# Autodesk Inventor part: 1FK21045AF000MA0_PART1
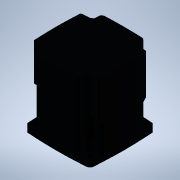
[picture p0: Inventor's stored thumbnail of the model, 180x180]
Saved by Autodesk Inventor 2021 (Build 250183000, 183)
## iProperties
Created: 2025-04
Part Number: 1FK21045AF000MA0_PART1
Material: Generic
Catalog Web Link: www.3dfindit.com
Description: -Servo synchronous motor
Document SubType Name: Modeling
Designer: psAdmin
Mass: 473.602 g
Surface Area: 436.509 cm^2
Volume: 473.602 cm^3
Density: 1 g/cm^3
Appearance: PSOLRGB-176-176-176
Category: PARTsolutions
Title: 1FK21045AF000MA0_PART1
Author: Cadenas PARTsolutions
Comments: Servo synchronous motor
Sending System: PARTsolutions
Preprocessor: ST-DEVELOPER v19.3
PSOL_IDENT_0: {$CADENAS_DATA/23d-libs/siemens_ag/_cat_/8b/0a/1fk21045af000ma0.prj},213 {VTYP=3D},{NB=1FK21045AF000
PSOL_IDENT_1: MA0_PART1},{LINA=1FK21045AF000MA0_PART1},{NN=1FK21045AF000MA0_PART1},{NOPRJ=TRUE},{DATE=19.08.2025 1
PSOL_IDENT_2: 4:00:48},{GEOMDATE=30.07.2025 02:00:28},{VERSION=},{LINEID=10},{WBVAR=},{WBNUMERIC=}  {NB=1FK21045AF
PSOL_IDENT_3: 000MA0_PART1},{LINA=1FK21045AF000MA0_PART1},{KT=DUMMY},{PREVIEW=../../../_pool_/a9/69/p_d211_xx_0081
PSOL_IDENT_4: 8j.png},{DESCSHORT=SIMOTICS S-1FK2 HD, SINAMICS S210 3AC 400V-480V, 2.4 Nm, 3000 rpm},{DESCLONG=SIMO
PSOL_IDENT_5: TICS S-1FK2 HD servo motor M0=2.4 Nm; PN = 0.75 kW at nN=3000 rpm (380-480 V); PN = 0.375 kW at nN=1
PSOL_IDENT_6: 500 rpm (200-240 V); degree of protection IP64; cylindrical shaft D19x40mm; absolute encoder 22-bit
PSOL_IDENT_7: + 12-bit multiturn (encoder AM22DQC); with OCC interface; plug size M17, rotatable; SIMOTICS S-1FK2
PSOL_IDENT_8: servomotorfor a wide range of uses in industrial environments. SIMOTICS S‑1FK2 servomotors are compa
PSOL_IDENT_9: ct synchronous motors with a high dynamic performance that set themselves apart as a result of their
PSOL_IDENT_10: high power density, degree of protection and overload capability. The motors are available in two v
PSOL_IDENT_11: ariants: as High Dynamic variant (highest dynamic performance as a result of the low intrinsic momen
PSOL_IDENT_12: t of inertia for applications demanding a high dynamic performance with low moved masses) - and as C
PSOL_IDENT_13: ompact variant (precise and stable closed-loop control for medium up to large moved masses as a resu
PSOL_IDENT_14: lt of a medium intrinsic moment of inertia). SIMOTICSS‑1FK2 servomotors fully exploit their strength
PSOL_IDENT_15: s in a system with the SINAMICSS210 frequency converter and simple connection using the one cable co
PSOL_IDENT_16: nnection (OCC). Advantages include the short control and positioning times, fast and precise correct
PSOL_IDENT_17: ion of disturbing quantities as well as stable control with a high dynamic performance. The servo mo
PSOL_IDENT_18: tors can be configured to address a wide range of requirements. For example with and without holding
PSOL_IDENT_19: brake, IP64 or IP65 degree of protection, singleturn or multiturn absolute encoders - to name just
PSOL_IDENT_20: a few. Further, the servomotors are available in different shaft heights extending from 20 to 100. A
PSOL_IDENT_21: shaft sealing ring is available to achieve an IP65 degree of protection and for subsequent mounting
PSOL_IDENT_22: at the motor or as spare part. SIMOTICS - the optimum motor for each and every motion control appli
PSOL_IDENT_23: cation.},{INTNO=195125050112},{SUPPLIERALTNO=1FK2104-5AF00-0MA0},{MANUID=1FK21045AF000MA0},{MANUNAME=
PSOL_IDENT_24: Siemens},{MANUTYPEDESC=Synchronous motor 1FK2-HD 2.4 NM},{AAU732=SIMOTICS},{AAO057=S-1FK2},{AAU734=S
PSOL_IDENT_25: IMOTICS S-1FK2 HD servo motor M0=2.4 Nm; PN = 0.75 kW at nN=3000 rpm (380-480 V); PN = 0.375 kW at n
PSOL_IDENT_26: N=1500 rpm (200-240 V); degree of protection IP64; cylindrical shaft D19x40mm; absolute encoder 22-b
PSOL_IDENT_27: it + 12-bit multiturn (encoder AM22DQC); with OCC interface; plug size M17, rotatable;},{AAW338=Sync
PSOL_IDENT_28: hronous motor 1FK2-HD 2.4 NM},{AAO742=SIMOTICS},{AAO663=4042948692912},{NOCUPEROU=1},{PRICEQUANTITY=
PSOL_IDENT_29: 1},{QUANTITYMIN=1},{QUANTITYINT=1},{CTN=85015100},{COO=DE},{AAO676=1FK2104-5AF00-0MA0},{AAO677=Sieme
PSOL_IDENT_30: ns AG},{ORDERUNIT=C62},{CONTENTUNIT=C62}
NB: 1FK21045AF000MA0_PART1
NT: Servo synchronous motor
NBSYN: $MANUID._PART1
LINA: 1FK21045AF000MA0_PART1
CATALOG: SIEMENS
PREVIEW: ../../../_pool_/a9/69/p_d211_xx_00818j.png
DESCSHORT: SIMOTICS S-1FK2 HD, SINAMICS S210 3AC 400V-480V, 2.4 Nm, 3000 rpm
DESCLONG: SIMOTICS S-1FK2 HD servo motor M0=2.4 Nm; PN = 0.75 kW at nN=3000 rpm (380-480 V); PN = 0.375 kW at nN=1500 rpm (200-240 V); degree of protection IP64; cylindri
INTNO: 195125050112
SUPPLIERALTNO: 1FK2104-5AF00-0MA0
MANUID: 1FK21045AF000MA0
MANUNAME: Siemens
MANUTYPEDESC: Synchronous motor 1FK2-HD 2.4 NM
AAU732: SIMOTICS
AAO057: S-1FK2
AAU734: SIMOTICS S-1FK2 HD servo motor M0=2.4 Nm; PN = 0.75 kW at nN=3000 rpm (380-480 V); PN = 0.375 kW at nN=1500 rpm (200-240 V); degree of protection IP64; cylindri
AAW338: Synchronous motor 1FK2-HD 2.4 NM
AAO742: SIMOTICS
AAO663: 4042948692912.0
NOCUPEROU: 1
PRICEQUANTITY: 1
QUANTITYMIN: 1
QUANTITYINT: 1
CTN: 85015100
COO: DE
ARTICLENO: 1FK21045AF000MA0_PART1
BOMINFO: 1FK21045AF000MA0_PART1
CREATOR: CADENAS GmbH
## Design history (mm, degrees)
feature "2025_04_17_15_40_42_0609"
node "ECLASS_CAX_IMPORTER_001_CP_0_XY"
node "ECLASS_CAX_IMPORTER_001_CP_0_YZ"
node "ECLASS_CAX_IMPORTER_001_CP_0_ZX"
node "ECLASS_CAX_IMPORTER_001_CP_0_X"
node "ECLASS_CAX_IMPORTER_001_CP_0_Y"
node "ECLASS_CAX_IMPORTER_001_CP_0_Z"
node "ECLASS_CAX_IMPORTER_001_CP_0_Center"
node "ECLASS_CAX_IMPORTER_001_CP_1_XY"
node "ECLASS_CAX_IMPORTER_001_CP_1_YZ"
node "ECLASS_CAX_IMPORTER_001_CP_1_ZX"
node "ECLASS_CAX_IMPORTER_001_CP_1_X"
node "ECLASS_CAX_IMPORTER_001_CP_1_Y"
node "ECLASS_CAX_IMPORTER_001_CP_1_Z"
node "ECLASS_CAX_IMPORTER_001_CP_1_Center"
body "Solid1"
